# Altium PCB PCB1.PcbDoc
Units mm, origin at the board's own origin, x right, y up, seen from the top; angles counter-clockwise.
Board outline 40 x 50.93 mm, 2 copper layers (Top Layer, Bottom Layer); 15 components, 10 nets, 36 pads, 0 vias.
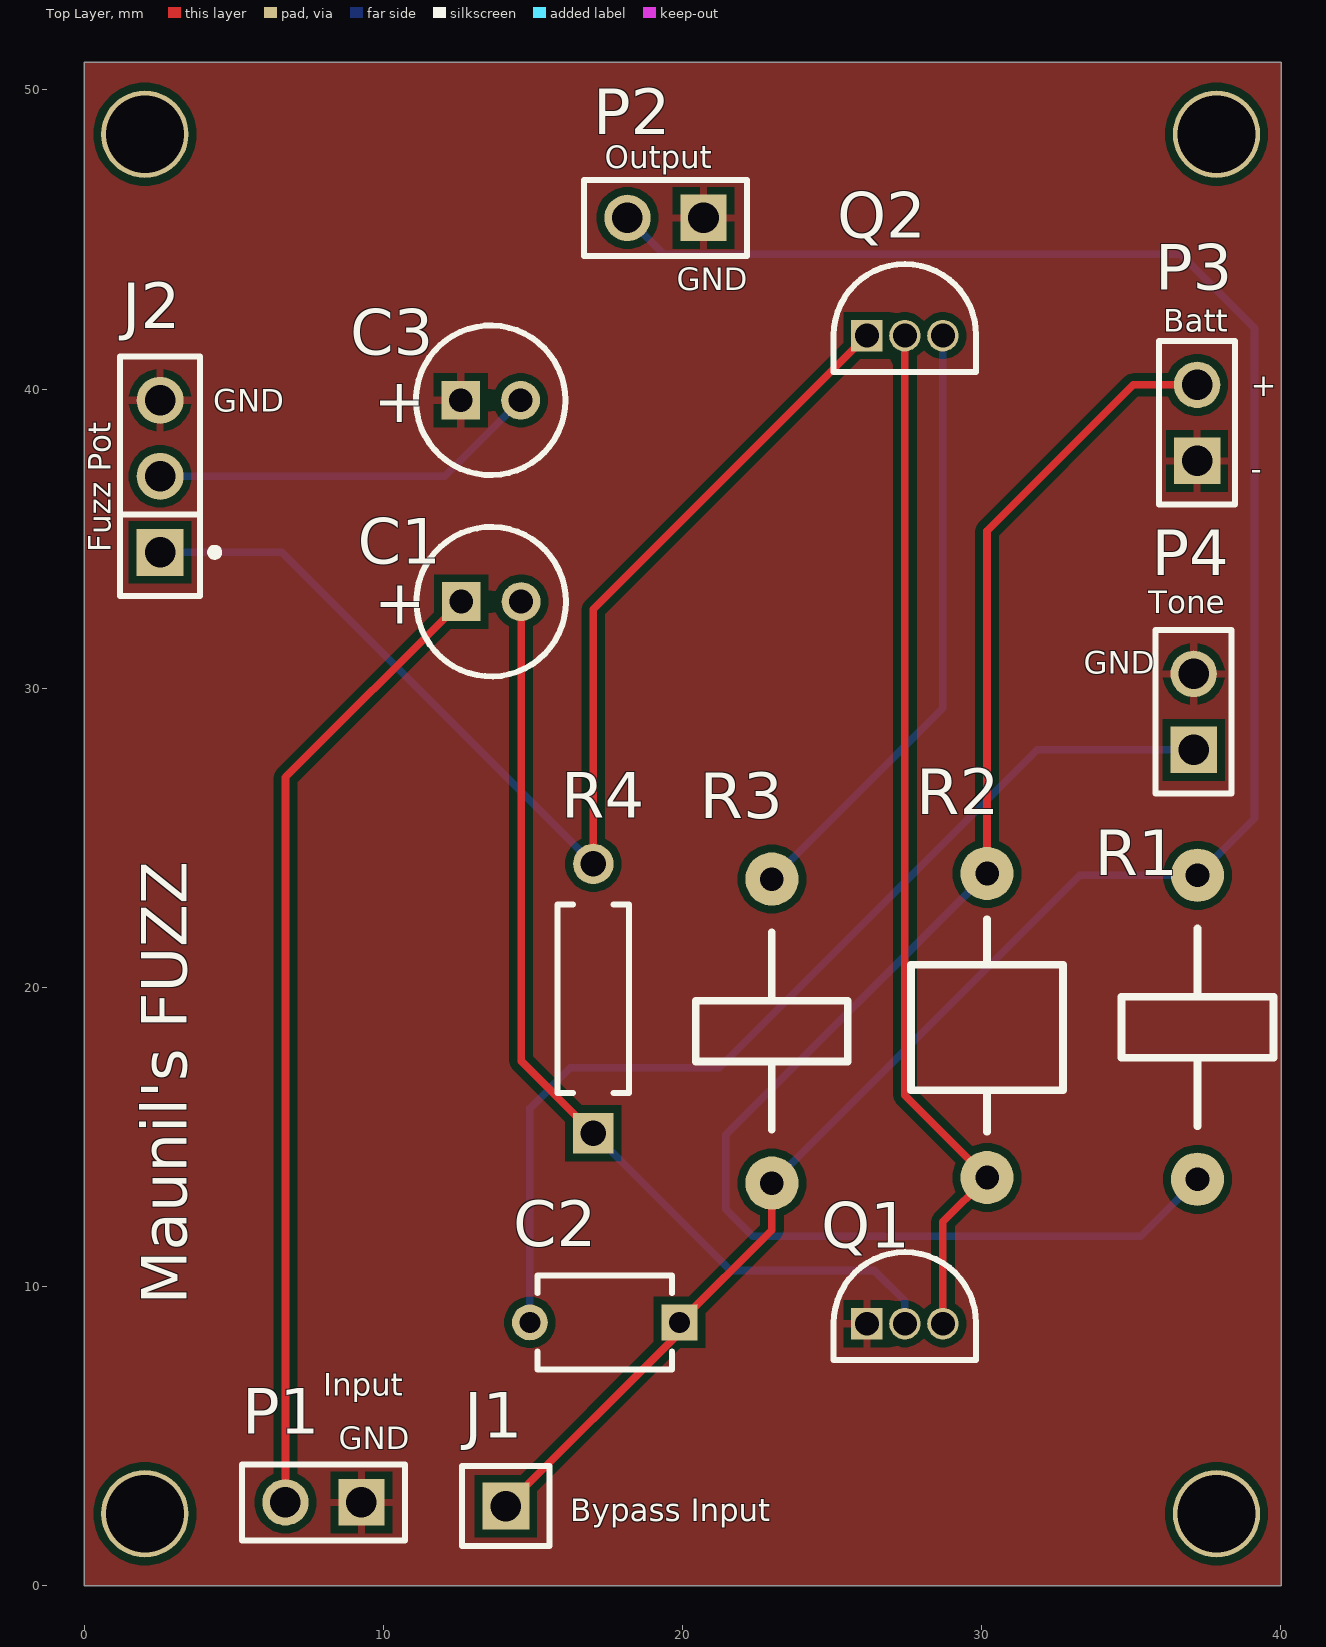
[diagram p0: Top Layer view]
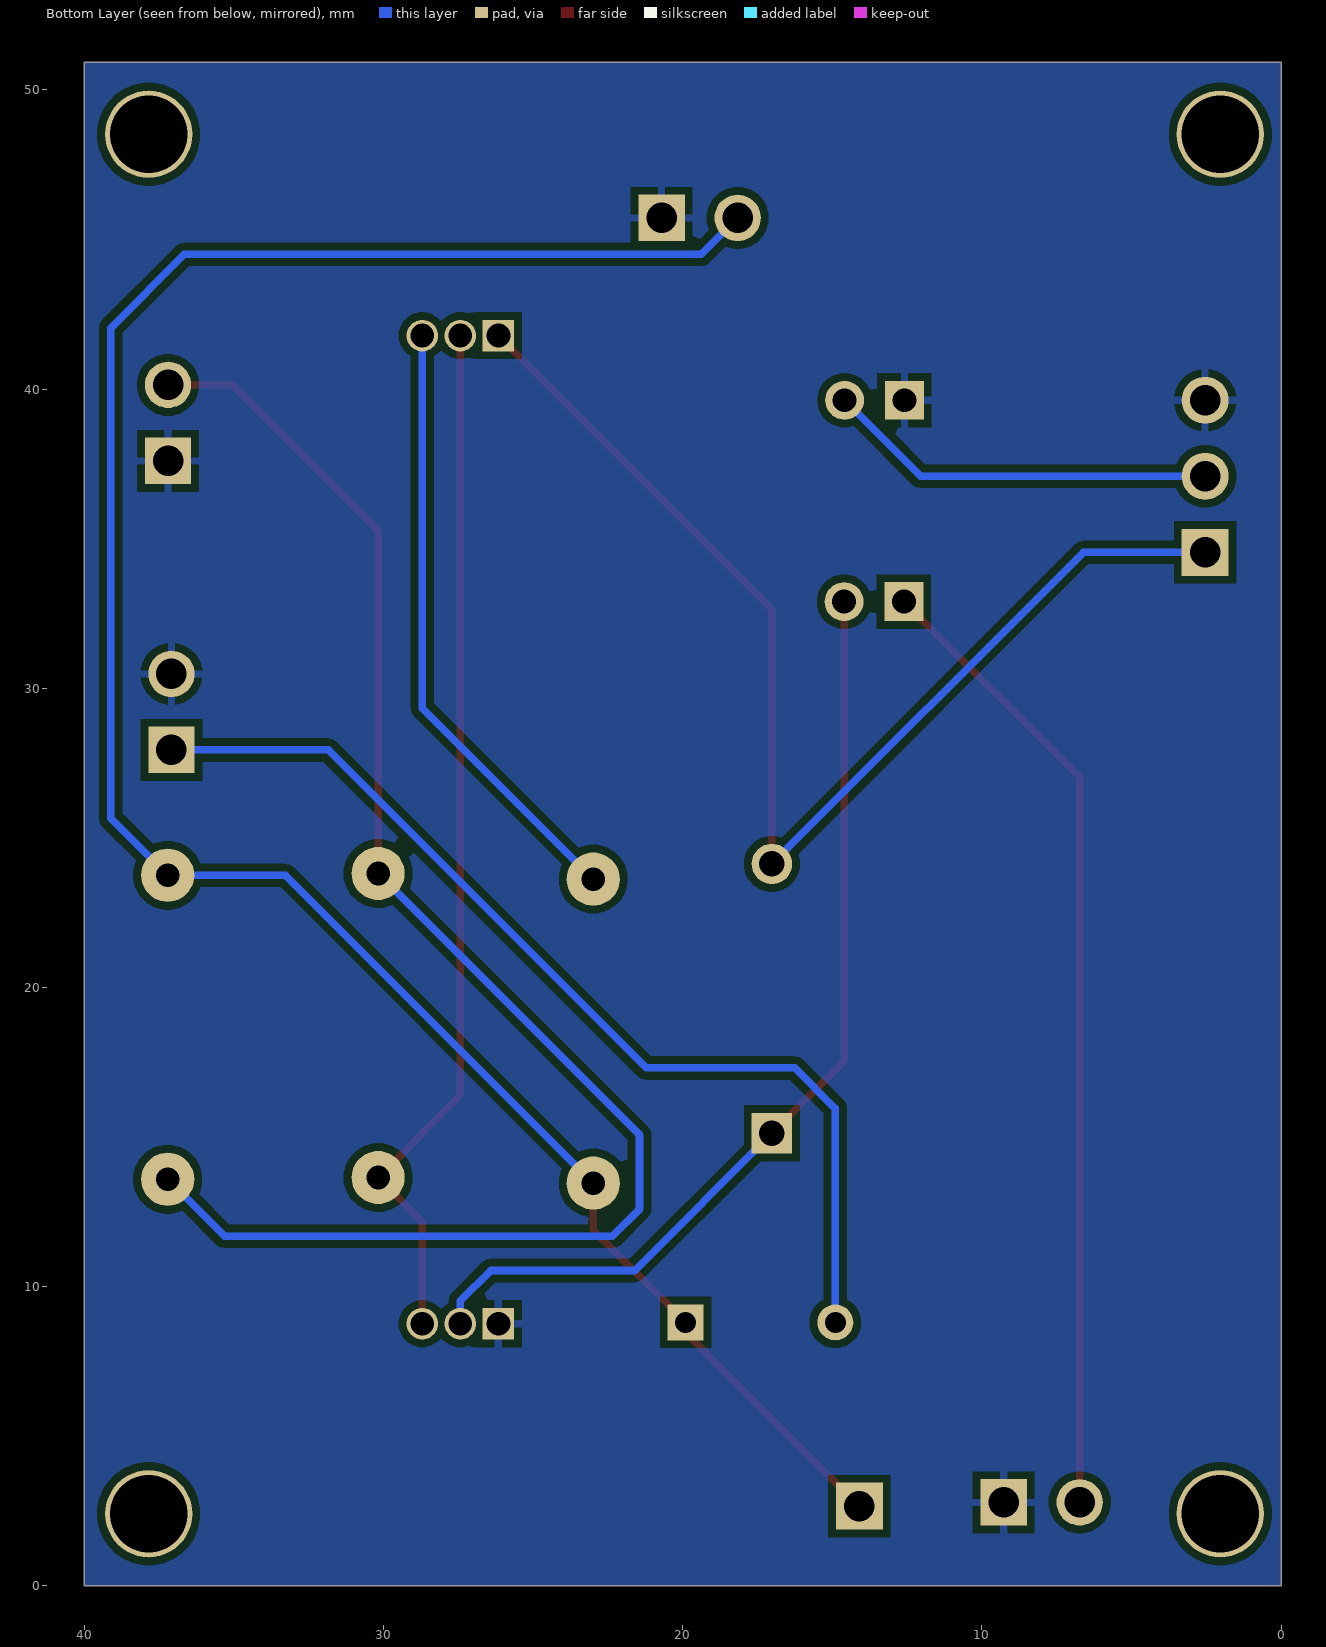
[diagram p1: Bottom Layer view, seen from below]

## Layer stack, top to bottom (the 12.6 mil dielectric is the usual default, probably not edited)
Top Solder: solder mask 0.0102, Solder Resist, Dk 3.5
Top Layer: signal copper 0.0356
Dielectric 1: dielectric 0.32, FR-4, Dk 4.8
Bottom Layer: signal copper 0.0356
Bottom Solder: solder mask 0.0102, Solder Resist, Dk 3.5

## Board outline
0,50.927 40.005,50.927 40.005,0 0,0

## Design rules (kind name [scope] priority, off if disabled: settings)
Clearance [All] p1: gap=0.254 ignorepadtopadclearanceinfootprint=TRUE
PolygonConnect [All] p1: connectstyle=Relief reliefconductorwidth=0.254 reliefentries=4 polygonreliefangle="90 Angle" airgapwidth=0.254
RoutingVias [All] p1: holewidth=0.711 width=1.27 viastyle="Through Hole" minholewidth=0.711 minwidth=1.27 maxholewidth=0.711 maxwidth=1.27
SolderMaskExpansion [All] p1: expansion=0.102 istentingtop=FALSE
SupplyNets "Schematic Supply Nets" [InNet('GND')] p1: voltage=0.000
Width [All] p1: maxlimit=0.381 minlimit=0.254 preferedwidth=0.381 minimp=50.000000 maximp=50.000000 favimp=50.000000
30 further rules are at their usual default settings.

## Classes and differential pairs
component class Sheetpcb: C1 C2 C3 J1 P1 P2 P3 P4 Q1 Q2 R1 R2 R3 R4

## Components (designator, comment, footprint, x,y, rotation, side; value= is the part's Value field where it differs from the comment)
C1 "ECA1HM2R2" CAPPR55-200-1100X500X1200 13.605,32.893 r0 top value=2.2µF
C2 "RDER72H103K1K1H03B" FP-RDE1K1-MFG 17.399,8.807 r180 top
C3 "ECA1HM220" CAPPR55-200-1100X500X1200 13.589,39.624 r0 top value=22µF
J1 "TSW-101-07-F-S" FP-TSW-101-07-F-S-MFG 14.097,2.667 r0 top
J2 "TSW-103-14-G-S" FP-TSW-103-14-G-S-MFG 2.54,37.084 r90 top
P1 "TSW-102-26-G-S" SMTC-TSW-102-26-XX-S 9.271,2.794 r180 top
P2 "TSW-102-26-G-S" SMTC-TSW-102-26-XX-S 20.701,45.72 r180 top
P3 "TSW-102-26-G-S" SMTC-TSW-102-26-XX-S 37.198,37.6 r90 top
P4 "TSW-102-26-G-S" SMTC-TSW-102-26-XX-S 37.084,27.94 r90 top
Q1 "2N3904BU" FAIR-TO-92 26.162,8.763 r0 top
Q2 "2N3904BU" FAIR-TO-92 26.162,41.783 r0 top
R1 "470 Ohm Generic Resistor" "470 Ohm Resistor" 37.211,13.589 r90 top value=470
R2 "33K Ohm Generic Through Hole Resistor" "Resistor 33K ohm" 30.177,13.649 r90 top value=33k
R3 "820 Ohm Generic Resistor" "Resistor 820 Ohm Generic" 22.987,13.462 r90 top value=820
R4 "MFR-25FBF52-100K" RESA60-630X240 17.018,19.63 r90 top value=100k

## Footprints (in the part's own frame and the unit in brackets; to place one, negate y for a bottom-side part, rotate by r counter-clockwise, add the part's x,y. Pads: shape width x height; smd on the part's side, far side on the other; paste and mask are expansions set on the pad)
"470 Ohm Resistor" [mil]
  round 70 hole 31: 1(0,0) 2(400,0)
  silkscreen extent 70,-100 330,100
CAPPR55-200-1100X500X1200 [mm] "THD, 2-Leads, Dia 5mm, Pin Spacing 2mm"
  rect 1.3x1.3 hole 0.8: 1(-1,0)
  round 1.3 hole 0.8: 2(1,0)
  silkscreen extent -2.5,-2.5 2.5,2.5, body extent -2.5,-2.5 2.45,2.5, height 12
FAIR-TO-92 [mm] "TO, 3-Leads, Body Dia 4.79mm, Pitch 1.27mm"
  rect 1.05x1.05 hole 0.8 mask+0.05: 1(0,0)
  round 1.05 hole 0.8 mask+0.05: 2(1.27,0) 3(2.54,0)
  silkscreen extent -1.11,-1.21 3.65,2.4, body extent -1.11,-1.21 3.65,2.4, height 5.33
FP-RDE1K1-MFG [mm]
  rect 1.2x1.2 hole 0.7 paste-2539.97 mask+0: 1(-2.5,0)
  round 1.2 hole 0.7 paste-2539.97 mask+0: 2(2.5,0)
  silkscreen extent -2.25,-1.58 2.25,1.57, body extent -3.2,-1.68 3.2,1.68, height 0.25
FP-TSW-101-07-F-S-MFG [mm]
  rect 1.57x1.57 hole 1.02 paste-2539.97 mask+0: 1(0,0)
  silkscreen extent -1.46,-1.34 1.46,1.34, body extent -1.56,-1.44 1.56,1.44, height 0.25
FP-TSW-103-14-G-S-MFG [mm]
  rect 1.57x1.57 hole 1.02 paste-2539.97 mask+0: 1(-2.54,0)
  round 1.57 hole 1.02 paste-2539.97 mask+0: 2(0,0) 3(2.54,0)
  silkscreen extent -4,-1.95 4,1.34, body extent -4.1,-1.44 4.1,1.44, height 0.25
RESA60-630X240 [mm] "Axial Resistor, 2-Leads, Dia 2.4mm, Body Length 6.3mm"
  rect 1.35x1.35 hole 0.85: 1(-4.5,0)
  round 1.35 hole 0.85: 2(4.5,0)
  silkscreen extent -3.15,-1.2 3.15,1.2, body extent -4.77,-1.19 4.77,1.2, height 2.4
"Resistor 33K ohm" [mil]
  round 70 hole 31: 1(0,0) 2(400,0)
  silkscreen extent 60,-100 340,100
"Resistor 820 Ohm Generic" [mil]
  round 70 hole 31: 1(0,0) 2(400,0)
  silkscreen extent 70,-100 330,100
SMTC-TSW-102-26-XX-S [mm] ".025 SQ Post Terminal Strip Assembly, 1x2 Pins, Vertical, 2.54mm Pitch, Male"
  rect 1.55x1.55 hole 1.02: 1(0,0)
  round 1.55 hole 1.02: 2(2.54,0)
  silkscreen extent -1.46,-1.27 4,1.27, body extent -1.4,-1.27 3.81,1.27, height 8.38

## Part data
C1: library part CMP-001-00029-7, "Aluminum Electrolytic Capacitor, 2.2 uF, +/- 20%, 50 V, -40 to 85 degC, 2-Pin THD, RoHS, Bulk", Capacitor Type=Electrolytic, Case/Package=Radial, Manufacturer=Panasonic, Max Operating Temperature=85°C, Min Operating Temperature=-40°C, Package Description="2-Pin Radial Lead, Dia 5 mm, Height 12 mm", Package Quantity=200, Package Reference=CAPPR55-200-1100X500X1200, Ripple Current=20mA, Tolerance=20%, Voltage Rating=50V
C2: library part CMP-06035-024341-1, "Ceramic Capacitor 10nF ±10% 500V X7R Radial"
C3: library part CMP-001-00027-7, "Aluminum Electrolytic Capacitor, 22 uF, +/- 20%, 50 V, -40 to 85 degC, 2-Pin THD, RoHS, Bulk", Capacitor Type=Electrolytic, Case/Package=Radial, Manufacturer=Panasonic, Max Operating Temperature=85°C, Min Operating Temperature=-40°C, Package Description="2-Pin Radial Lead, Dia 5 mm, Height 12 mm", Package Quantity=200, Package Reference=CAPPR55-200-1100X500X1200, Ripple Current=100mA, Tolerance=20%, Voltage Rating=50V
J1: library part CMP-02766-001403-1, "CONN HEADER VERT 1POS", Flammability Rating="UL94 V-0", Insulation Color=Black, Max Operating Temperature=125°C, Min Operating Temperature=-55°C
J2: library part CMP-02766-001743-1, "CONN HEADER VERT 3POS 2.54MM", Color=Black, Flammability Rating="UL94 V-0", Max Current Rating=7.6A, Max Operating Temperature=125°C, Max Voltage Rating (AC)=550V, Min Operating Temperature=-55°C, Package Quantity=1
P1 P2 P3 P4: library part CMP-1024-00327-1, "0.025\" SQ Post Header, Through-hole, Vertical, -55 to 125 degC, 2.54 mm Pitch, 2-Pin, Male, RoHS", Manufacturer=Samtec, Temperature Range="-55 to 125 degC"
Q1 Q2: library part CMP-2000-04944-1, "NPN General-Purpose Amplifier, 40 V VCEO, 0.2 A, -55 to 150 degC, 2-Pin TO-92, RoHS, Bulk", Manufacturer=FairchildSemiconductor, Maximum Collector Base Voltage=60V, Maximum Collector Emitter Saturation Voltage=0.2@1mA@10mA, Maximum Collector Emitter Voltage=40V, Maximum DC Collector Current=0.2A, Maximum Operating Frequency=300(Min)MHz, Maximum Power Dissipation=625mW, Minimum DC Current Gain=40@0.1mA@1V, Operating Temperature=-55to150degC, Package=3TO-92, Package Description="3-Pin Transistor Outline Package, Body Dia 4.79 mm, Pitch 1.27 mm", Package Reference=TO-92
R1: library part CMP-009-00178-1, Power=250mW
R2: library part CMP-009-00177-1, Power=250mW
R3: library part CMP-009-00179-1, Power=250mW
R4: library part CMP-009-00045-4, "Axial Resistor, 100 KOhm, +/- 1%, 0.25 W, -55 to 155 degC, 2-Pin THD, RoHS, Bulk", Case/Package=Axial, Manufacturer=Yageo, Max Operating Temperature=155°C, Min Operating Temperature=-55°C, Package Description="2-Pin Axial Lead, Dia 2.4 mm, Body Length 6.3 mm", Package Quantity=200, Package Reference=MFR-25, Power=250mW, Tolerance=1%, Voltage Rating=250V

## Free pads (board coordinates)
  round 2.921 hole 2.6 unplated: 1(2.032,48.514) 2(37.846,48.514) 3(37.846,2.413)
  round 2.921 hole 2.6: 4(2.032,2.413)

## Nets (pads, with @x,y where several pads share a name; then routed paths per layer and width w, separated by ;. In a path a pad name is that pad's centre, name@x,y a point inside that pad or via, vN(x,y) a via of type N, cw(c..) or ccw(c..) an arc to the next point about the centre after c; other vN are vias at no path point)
GND: C3.1 J2.3 P1.1 P2.1 P3.1 P4.2 Q1.1
NetC1_1: C1.1 P1.2 | length 32.5
  Top Layer w0.254: P1.2 6.731,27.019 C1.1
NetC1_2: C1.2 Q1.2 R4.1 | length 32.3
  Top Layer w0.254: C1.2 14.605,17.543 R4.1
  Bottom Layer w0.254: R4.1 21.607,10.541 26.416,10.541 27.432,9.525 Q1.2
NetC2_1: C2.1 J1.1 P2.2 R1.2 R3.1 | length 74.5
  Top Layer w0.254: J1.1 19.899,8.469 C2.1 22.987,11.895 R3.1
  Bottom Layer w0.254: P2.2 19.38,44.501 36.652,44.501 39.116,42.037 39.116,25.654 R1.2 33.274,23.749 R3.1
NetC2_2: C2.2 P4.1 | length 34.3
  Bottom Layer w0.254: C2.2 14.899,15.955 16.256,17.312 21.224,17.312 31.852,27.94 P4.1
NetC3_2: C3.2 J2.2 | length 13.1
  Bottom Layer w0.254: J2.2 12.049,37.084 C3.2
NetJ2_1: J2.1 Q2.1 R4.2 | length 40.2
  Top Layer w0.254: R4.2 17.018,32.639 Q2.1
  Bottom Layer w0.254: J2.1 6.604,34.544 R4.2
NetP3_2: P3.2 R1.1 R2.2 | length 52.3
  Top Layer w0.254: R2.2 30.177,35.257 35.06,40.14 P3.2
  Bottom Layer w0.254: R2.2 21.442,15.075 21.442,12.594 22.352,11.684 35.306,11.684 R1.1
NetQ1_3: Q1.3 Q2.2 R2.1 | length 34.8
  Top Layer w0.254: Q2.2 27.432,16.394 R2.1 28.702,12.174 Q1.3
NetQ2_3: Q2.3 R3.2 | length 20.5
  Bottom Layer w0.254: R3.2 28.702,29.337 Q2.3

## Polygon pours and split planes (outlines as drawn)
GND on Top Layer "GND_L01_P001" (solid, pour order 1): 0,0 40.005,0 40.005,50.927 0,50.927
GND on Bottom Layer "GND_L02_P000" (solid, pour order 0): 0,0 40.005,0 40.005,50.927 0,50.927

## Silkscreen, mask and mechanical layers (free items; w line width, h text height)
Top Overlay:
  text "Output" at 17.399,47.371 h0.76
  text "GND" at 19.812,43.307 h0.76
  text "Batt" at 36.068,41.91 h0.76
  text "+" at 38.989,39.751 h0.76
  text "GND" at 4.318,39.243 h0.76
  text "-" at 38.989,36.957 h0.76
  text "Fuzz Pot" at 0.889,34.544 h0.76 r90
  text "Tone" at 35.56,32.512 h0.76
  text "GND" at 33.401,30.48 h0.76
  text "Maunil's FUZZ" at 3.429,9.398 h1.52 r90
  text "Input" at 8.001,6.35 h0.76
  text "GND" at 8.509,4.572 h0.76
  text "Bypass Input" at 16.256,2.159 h0.76

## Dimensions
2.032,48.514 to 2.032,2.413 on Top Overlay
37.846,2.413 to 37.846,48.514 on Top Overlay
2.032,2.413 to 37.846,2.413 on Top Overlay
2.032,48.514 to 37.846,48.514 on Top Overlay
